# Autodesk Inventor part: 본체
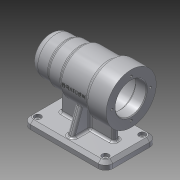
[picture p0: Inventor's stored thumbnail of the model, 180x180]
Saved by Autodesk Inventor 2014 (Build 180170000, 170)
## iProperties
Created: 2016-06
Part Number: 본체
Material: 알루미늄 6061
Document SubType Name: Modeling
Designer: USER
Density: 2.71 g/cm^3
Appearance: 알루미늄 - 평지
Mass: 673.104 g
Surface Area: 647.407 cm^2
Volume: 248.378 cm^3
Author: USER
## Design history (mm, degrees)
sketch "스케치1"
  geometry: L1 (-56, -35)-(56, -35); L2 (56, -35)-(56, 35); L3 (56, 35)-(-56, 35); L4 (-56, 35)-(-56, -35); 3 further points
  constraints: 8 end point, 2 midpoint, 2 parallel, 1 horizontal, 1 horizontal alignment, 1 perpendicular, 1 vertical alignment
  dimensions: "d0" = 112 distance of L3.end L2.end; "d1" = 70 distance of L1.end L2.end
extrude "돌출1" new body sketch "스케치1" distance "d2" = 10; taper "d3" = 0 deg
sketch "스케치2"
  geometry: L1 (61.417, 70)-(-63.585, 70); L2 (-56, 0)-(-56, 10) reference; L3 (-56, 70)-(-56, 104); L4 (-56, 104)-(-28, 104); L5 (-28, 104)-(-28, 100); L6 (-28, 100)-(11, 100); L7 (11, 100)-(11, 97); L8 (11, 97)-(31, 97); L9 (31, 97)-(31, 95); L10 (31, 95)-(56, 95); L11 (56, 95)-(56, 70); 1 further point
  constraints: 20 end point, 6 parallel, 2 perpendicular, 2 point on line, 1 collinear, 1 horizontal, 1 vertical alignment
  dimensions: "d4" = 70 distance from line of point (0, 0) L1; "d5" = 68 diameter of L4 L1; "d6" = 60 diameter of L6 L1; "d7" = 54 diameter of L8 L1; "d8" = 50 diameter of L10 L1; "d9" = 25 distance of L9.end L10.end; "d10" = 45 distance from line of L7.end L11; "d11" = 84 distance from line of L4.end L11; "d12" = 112 distance between parallel lines of L3 L11
revolve "회전1" sketch "스케치2" stored, may be unused: angle "d13" = 90 deg
sketch "스케치3"
  geometry: L1 (-56, 36)-(-56, 104) reference; L2 (-56, 70)-(58.922, 70); L3 (-56, 91)-(-41, 91); L4 (-41, 91)-(-41, 94); L5 (-41, 94)-(13, 94); L6 (13, 94)-(13, 91); L7 (13, 91)-(25, 91); L8 (25, 91)-(25, 87.5); L9 (25, 87.5)-(43, 87.5); L10 (43, 87.5)-(43, 86); L11 (43, 86)-(47, 86); L12 (47, 86)-(47, 80.5); L13 (47, 80.5)-(50, 80.5); L14 (50, 80.5)-(50, 70); 1 further point
  constraints: 26 end point, 7 parallel, 6 perpendicular, 2 point on line, 1 midpoint
  dimensions: "d14" = 21 diameter of L13 L2; "d15" = 32 diameter of L11 L2; "d16" = 35 diameter of L9 L2; "d17" = 42 diameter of L7 L2; "d18" = 48 diameter of L5 L2; "d19" = 42 diameter of L3 L2; "d20" = 15 distance of L3.start L3.end; "d21" = 54 distance of L4.end L5.end; "d22" = 12 distance of L6.end L7.end; "d23" = 18 distance of L8.end L9.end; "d24" = 3 distance of L12.end L13.end; "d25" = 4 distance of L10.end L11.end
revolve "회전2" sketch "스케치3" stored, may be unused: angle "d26" = 90 deg
sketch "스케치4"
  geometry: L1 (56, -35)-(56, 35) reference; L2 (-56, 35)-(-56, -35) reference; L3 (-36, -4)-(36, -4); L4 (36, -4)-(36, 4); L5 (36, 4)-(-36, 4); L6 (-36, 4)-(-36, -4); 2 further points
  constraints: 8 end point, 2 parallel, 1 horizontal, 1 horizontal alignment, 1 midpoint, 1 perpendicular
  dimensions: "d27" = 20 distance between parallel lines of L2 L6; "d28" = 20 distance between parallel lines of L1 L4; "d29" = 8 distance of L5.end L3.start
extrude "돌출2" join sketch "스케치4" stored distance "d30" = 10; taper "d31" = 0 deg
sketch "스케치5"
  geometry: L1 (35, 10)-(-35, 10) reference; L2 (4, 10)-(4, 45.322) reference; L3 (-4, 10)-(4, 10) reference; L4 (-4, 10)-(-4, 45.322) reference; L5 (-28, 10)-(-15.509, 44.32); L6 (15.509, 44.32)-(28, 10); L7 (-35, 0)-(-35, 10) reference; A1 r 25 centre (0, 70) between (-4, 45.322) and (4, 45.322) reference; A2 r 30 centre (0, 70) between (4, 40.268) and (-4, 40.268) reference; 1 further point
  constraints: 4 end point, 2 point on circle, 2 point on line
  dimensions: "d32" = 110 deg angle of L1 L6; "d33" = 110 deg angle of L1 L5; "d34" = 7 distance from line of L5.start L7; "d35" = 7 distance of L1.start L6.end
  node "투영된 루프1"
feature "리브1" dims "d36" = 1, "d37" = 8, "d38" = 0, "d39" = 0, "d40" = 1, "d41" = 1
feature "리브2" dims "d42" = 1, "d43" = 8, "d44" = 0, "d45" = 0, "d46" = 1, "d47" = 1
fillet "모깎기1" dims "d48" = 10
fillet "모깎기2" dims "d49" = 3
fillet "모깎기3" dims "d50" = 3
fillet "모깎기4" dims "d51" = 10
chamfer "모따기1" distance "d52" = 4; stored, may be unused: second distance "d53" = 2, angle "d54" = 45 deg
fillet "모깎기5" dims "d55" = 3
fillet "모깎기6" dims "d56" = 0.3
sketch "스케치6"
  geometry: C1 r 21 at (0, 0) reference; 2 further points
  constraints: 1 vertical alignment
  dimensions: "d57" = 26 distance of C1.centre point (0, 26)
hole "구멍1" sketch "스케치6" at (0, 26) diameter "d58" = 3.242; stored, may be unused: countersink angle "d62" = 90 deg, drill point angle "d64" = 118 deg; dims "d59" = 8, "d60" = 4, "d61" = 2, "d63" = 11
fillet "모깎기7" dims "d68" = 3
fillet "모깎기8" dims "d69" = 3
fillet "모깎기9" dims "d70" = 3
node "작업 평면2"
sketch "스케치7"
  geometry: L1 (47.5, 1.621)-(47.5, -1.621) reference; 3 further points
  constraints: 1 horizontal alignment, 1 midpoint, 1 other
  dimensions: "d71" = 48 distance from line of L1 point (-0.5, 0)
feature "엠보싱1" sketch "스케치7" dims "d0" = 112, "d1" = 70, "d72" = 0.5, "d73" = 0
sketch "스케치8"
  geometry: A1 r 6 centre (46, -25) between (46, -31) and (52, -25) reference; 2 further points
  constraints: 1 coincident
  dimensions: "d74" = 46 horizontal distance of point (46, -25) point (0, 0) (derived); "d75" = 25 vertical distance of point (46, -25) point (0, 0) (derived)
hole "구멍2" sketch "스케치8" at (46, -25) diameter "d76" = 5; stored, may be unused: countersink angle "d80" = 90 deg, drill point angle "d82" = 118 deg; dims "d77" = 5, "d78" = 9, "d79" = 4, "d81" = 11
chamfer "모따기2" distance "d89" = 1; stored, may be unused: second distance "d90" = 2, angle "d91" = 45 deg
node "솔리드1"
pattern_circular "원형 패턴1" dims angle "d66" = 360 deg
pattern_linear "직사각형 패턴1" dims "d85" = 92
